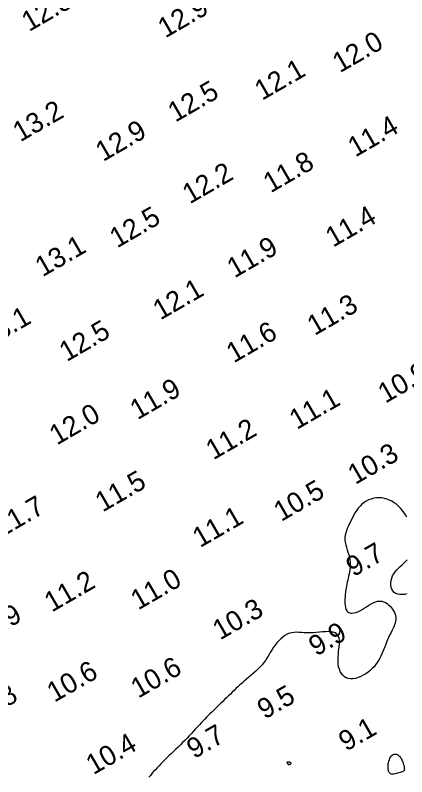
# Model space of a CAD drawing. Extents: x 3024098 to 3056816, y 418252 to 509144.
# Drawn here: x 3036317.9 to 3036415.8, y 419350.7 to 419541.3 of the extents above; entities that cross this region are included whole.
import ezdxf

# ---------------------------------------------------------------- set-up
doc = ezdxf.new("R2010")
doc.units = 0
doc.layers.add('V-CHAN-CONT-EL10', color=7, linetype='Continuous')
doc.layers.add('V-TOPO-SOUN-0911', color=7, linetype='Continuous')

msp = doc.modelspace()

# ---------------------------------------------------------------- linework, layer by layer
at = {"layer": 'V-CHAN-CONT-EL10'}
for points in [[(3036415.77, 419415.72), (3036415.43, 419416.31), (3036415.06, 419416.89), (3036414.64, 419417.44), (3036414.19, 419417.96), (3036413.7, 419418.45), (3036413.18, 419418.9), (3036412.62, 419419.31), (3036412.04, 419419.67), (3036411.44, 419419.97), (3036410.81, 419420.21), (3036410.17, 419420.39), (3036409.51, 419420.5), (3036408.84, 419420.54), (3036408.18, 419420.5), (3036407.52, 419420.4), (3036406.87, 419420.22), (3036406.24, 419419.99), (3036405.64, 419419.69), (3036405.08, 419419.34), (3036404.55, 419418.93), (3036404.08, 419418.48), (3036403.65, 419417.97), (3036403.25, 419417.44), (3036402.89, 419416.87), (3036402.56, 419416.29), (3036402.25, 419415.7), (3036401.96, 419415.1), (3036401.67, 419414.51), (3036401.4, 419413.94), (3036401.13, 419413.37), (3036400.89, 419412.82), (3036400.68, 419412.26), (3036400.51, 419411.71), (3036400.39, 419411.15), (3036400.32, 419410.58), (3036400.32, 419409.99), (3036400.39, 419409.4), (3036400.51, 419408.79), (3036400.68, 419408.17), (3036400.87, 419407.54), (3036401.07, 419406.91), (3036401.25, 419406.27), (3036401.42, 419405.64), (3036401.54, 419405.01), (3036401.6, 419404.39), (3036401.62, 419403.78), (3036401.6, 419403.18), (3036401.54, 419402.59), (3036401.45, 419402.02), (3036401.34, 419401.46), (3036401.23, 419400.92), (3036401.11, 419400.4), (3036401, 419399.9), (3036400.89, 419399.41), (3036400.79, 419398.93), (3036400.69, 419398.45), (3036400.61, 419397.97), (3036400.53, 419397.47), (3036400.45, 419396.96), (3036400.39, 419396.42), (3036400.34, 419395.86), (3036400.3, 419395.28), (3036400.28, 419394.7), (3036400.29, 419394.13), (3036400.34, 419393.59), (3036400.43, 419393.09), (3036400.57, 419392.66), (3036400.76, 419392.29), (3036401.01, 419392.02), (3036401.32, 419391.83), (3036401.68, 419391.71), (3036402.08, 419391.68), (3036402.52, 419391.73), (3036403, 419391.84), (3036403.51, 419392.02), (3036404.03, 419392.27), (3036404.58, 419392.57), (3036405.13, 419392.92), (3036405.7, 419393.28), (3036406.27, 419393.64), (3036406.83, 419393.98), (3036407.39, 419394.28), (3036407.94, 419394.51), (3036408.48, 419394.66), (3036409, 419394.71), (3036409.5, 419394.66), (3036409.97, 419394.53), (3036410.42, 419394.33), (3036410.84, 419394.06), (3036411.23, 419393.76), (3036411.59, 419393.41), (3036411.92, 419393.04), (3036412.21, 419392.66), (3036412.46, 419392.27), (3036412.67, 419391.86), (3036412.84, 419391.44), (3036412.95, 419391.01), (3036413.02, 419390.57), (3036413.03, 419390.12), (3036412.98, 419389.66), (3036412.87, 419389.19), (3036412.71, 419388.71), (3036412.51, 419388.22), (3036412.28, 419387.72), (3036412.02, 419387.21), (3036411.75, 419386.68), (3036411.48, 419386.14), (3036411.22, 419385.59), (3036410.97, 419385.02), (3036410.74, 419384.45), (3036410.51, 419383.86), (3036410.28, 419383.28), (3036410.05, 419382.69), (3036409.82, 419382.1), (3036409.57, 419381.52), (3036409.31, 419380.94), (3036409.02, 419380.38), (3036408.71, 419379.83), (3036408.36, 419379.29), (3036407.99, 419378.77), (3036407.58, 419378.27), (3036407.13, 419377.79), (3036406.64, 419377.33), (3036406.1, 419376.9), (3036405.52, 419376.5), (3036404.9, 419376.13), (3036404.25, 419375.81), (3036403.6, 419375.54), (3036402.95, 419375.35), (3036402.31, 419375.24), (3036401.71, 419375.21), (3036401.14, 419375.29), (3036400.63, 419375.48), (3036400.17, 419375.76), (3036399.77, 419376.13), (3036399.43, 419376.58), (3036399.14, 419377.08), (3036398.91, 419377.64), (3036398.74, 419378.24), (3036398.63, 419378.86), (3036398.58, 419379.49), (3036398.58, 419380.13), (3036398.61, 419380.78), (3036398.67, 419381.42), (3036398.74, 419382.06), (3036398.82, 419382.68), (3036398.88, 419383.28), (3036398.93, 419383.86), (3036398.94, 419384.41), (3036398.91, 419384.93), (3036398.83, 419385.4), (3036398.7, 419385.83), (3036398.49, 419386.2), (3036398.21, 419386.51), (3036397.85, 419386.75), (3036397.39, 419386.92), (3036396.83, 419387.02), (3036396.19, 419387.05), (3036395.49, 419387.03), (3036394.73, 419386.98), (3036393.95, 419386.91), (3036393.15, 419386.83), (3036392.35, 419386.77), (3036391.57, 419386.74), (3036390.83, 419386.75), (3036390.13, 419386.79), (3036389.45, 419386.83), (3036388.81, 419386.87), (3036388.19, 419386.89), (3036387.58, 419386.86), (3036387, 419386.78), (3036386.43, 419386.63), (3036385.86, 419386.39), (3036385.31, 419386.07), (3036384.77, 419385.68), (3036384.26, 419385.24), (3036383.77, 419384.75), (3036383.3, 419384.23), (3036382.86, 419383.69), (3036382.46, 419383.14), (3036382.09, 419382.59), (3036381.75, 419382.04), (3036381.42, 419381.49), (3036381.1, 419380.94), (3036380.76, 419380.4), (3036380.41, 419379.85), (3036380.03, 419379.31), (3036379.6, 419378.78), (3036379.12, 419378.24), (3036378.6, 419377.71), (3036378.05, 419377.18), (3036377.47, 419376.66), (3036376.88, 419376.15), (3036376.29, 419375.64), (3036375.7, 419375.14), (3036375.13, 419374.66), (3036374.59, 419374.18), (3036374.06, 419373.71), (3036373.56, 419373.25), (3036373.07, 419372.79), (3036372.6, 419372.34), (3036372.12, 419371.89), (3036371.66, 419371.44), (3036371.19, 419370.98), (3036370.71, 419370.52), (3036370.24, 419370.05), (3036369.76, 419369.59), (3036369.28, 419369.12), (3036368.81, 419368.66), (3036368.34, 419368.21), (3036367.88, 419367.76), (3036367.44, 419367.32), (3036367, 419366.88), (3036366.57, 419366.46), (3036366.14, 419366.04), (3036365.72, 419365.61), (3036365.29, 419365.17), (3036364.85, 419364.73), (3036364.4, 419364.26), (3036363.94, 419363.77), (3036363.46, 419363.25), (3036362.96, 419362.71), (3036362.45, 419362.16), (3036361.92, 419361.58), (3036361.39, 419361), (3036360.84, 419360.42), (3036360.28, 419359.84), (3036359.72, 419359.27), (3036359.16, 419358.71), (3036358.6, 419358.15), (3036358.04, 419357.61), (3036357.48, 419357.08), (3036356.92, 419356.55), (3036356.38, 419356.03), (3036355.84, 419355.52), (3036355.32, 419355.01), (3036354.81, 419354.5), (3036354.31, 419354), (3036353.83, 419353.5), (3036353.36, 419353), (3036352.92, 419352.51), (3036352.48, 419352.02), (3036352.07, 419351.54), (3036351.67, 419351.07), (3036351.29, 419350.6)], [(3036415.81, 419396.48), (3036415.22, 419396.36), (3036414.63, 419396.32), (3036414.06, 419396.35), (3036413.52, 419396.45), (3036413.04, 419396.63), (3036412.61, 419396.88), (3036412.26, 419397.22), (3036412.01, 419397.64), (3036411.84, 419398.12), (3036411.76, 419398.66), (3036411.77, 419399.23), (3036411.85, 419399.81), (3036412, 419400.4), (3036412.22, 419400.98), (3036412.51, 419401.52), (3036412.86, 419402.03), (3036413.26, 419402.49), (3036413.69, 419402.93), (3036414.14, 419403.35), (3036414.6, 419403.76), (3036415.05, 419404.17), (3036415.47, 419404.59), (3036415.86, 419405.03)]]:
    msp.add_lwpolyline(points, dxfattribs=at)
for points in [[(3036411.1, 419353.51), (3036411.14, 419353.89), (3036411.21, 419354.28), (3036411.3, 419354.66), (3036411.41, 419355.03), (3036411.55, 419355.37), (3036411.72, 419355.68), (3036411.92, 419355.94), (3036412.14, 419356.15), (3036412.38, 419356.3), (3036412.64, 419356.38), (3036412.91, 419356.41), (3036413.18, 419356.37), (3036413.45, 419356.27), (3036413.72, 419356.1), (3036413.96, 419355.86), (3036414.19, 419355.56), (3036414.4, 419355.21), (3036414.59, 419354.82), (3036414.75, 419354.41), (3036414.89, 419354), (3036415, 419353.6), (3036415.08, 419353.24), (3036415.13, 419352.92), (3036415.16, 419352.67), (3036415.15, 419352.47), (3036415.11, 419352.32), (3036415.04, 419352.21), (3036414.92, 419352.11), (3036414.78, 419352.04), (3036414.59, 419351.97), (3036414.37, 419351.89), (3036414.1, 419351.8), (3036413.81, 419351.7), (3036413.49, 419351.6), (3036413.17, 419351.52), (3036412.84, 419351.45), (3036412.52, 419351.4), (3036412.22, 419351.38), (3036411.96, 419351.41), (3036411.73, 419351.48), (3036411.54, 419351.6), (3036411.38, 419351.77), (3036411.26, 419351.97), (3036411.18, 419352.21), (3036411.12, 419352.49), (3036411.08, 419352.8), (3036411.08, 419353.14)], [(3036385.95, 419354.14), (3036385.92, 419354.18), (3036385.88, 419354.22), (3036385.86, 419354.26), (3036385.83, 419354.3), (3036385.83, 419354.34), (3036385.83, 419354.37), (3036385.85, 419354.4), (3036385.88, 419354.43), (3036385.94, 419354.45), (3036386, 419354.47), (3036386.08, 419354.48), (3036386.16, 419354.48), (3036386.24, 419354.48), (3036386.32, 419354.48), (3036386.4, 419354.46), (3036386.47, 419354.44), (3036386.54, 419354.42), (3036386.59, 419354.39), (3036386.65, 419354.35), (3036386.69, 419354.31), (3036386.73, 419354.27), (3036386.75, 419354.23), (3036386.78, 419354.19), (3036386.79, 419354.15), (3036386.8, 419354.1), (3036386.8, 419354.06), (3036386.79, 419354.02), (3036386.77, 419353.98), (3036386.74, 419353.94), (3036386.71, 419353.9), (3036386.66, 419353.87), (3036386.61, 419353.84), (3036386.55, 419353.82), (3036386.49, 419353.79), (3036386.42, 419353.78), (3036386.36, 419353.76), (3036386.3, 419353.76), (3036386.24, 419353.76), (3036386.2, 419353.76), (3036386.17, 419353.77), (3036386.15, 419353.79), (3036386.13, 419353.81), (3036386.13, 419353.83), (3036386.12, 419353.85), (3036386.12, 419353.88), (3036386.12, 419353.91), (3036386.12, 419353.93), (3036386.12, 419353.95), (3036386.11, 419353.97), (3036386.1, 419353.99), (3036386.08, 419354.01), (3036386.06, 419354.03), (3036386.04, 419354.05), (3036386.02, 419354.08), (3036385.98, 419354.11)]]:
    msp.add_lwpolyline(points, close=True, dxfattribs=at)

# ---------------------------------------------------------------- texts
at = {"layer": 'V-TOPO-SOUN-0911'}
for s, p in [('12.8 ', (3036321.34, 419537.05)), ('12.9 ', (3036355.4, 419535.44)), ('12.0 ', (3036399.05, 419526.74)), ('12.1 ', (3036379.59, 419519.84)), ('12.5 ', (3036357.91, 419514.38)), ('13.2 ', (3036319.14, 419509.45)), ('11.4 ', (3036402.9, 419505.65)), ('12.9 ', (3036339.84, 419504.53)), ('11.8 ', (3036381.74, 419496.69)), ('12.2 ', (3036361.53, 419493.94)), ('12.5 ', (3036343.34, 419482.91)), ('11.4 ', (3036397.32, 419483.08)), ('13.1 ', (3036324.73, 419475.71)), ('11.9 ', (3036372.69, 419475.4)), ('12.1 ', (3036354.16, 419464.88)), ('11.3 ', (3036392.73, 419461)), ('13.1 ', (3036310.96, 419457.93)), ('12.5 ', (3036330.75, 419454.47)), ('11.6 ', (3036372.52, 419454.15)), ('10.9 ', (3036410.42, 419444.07)), ('11.9 ', (3036348.44, 419439.93)), ('11.1 ', (3036388.28, 419437.49)), ('12.0 ', (3036328.28, 419433.6)), ('11.2 ', (3036367.4, 419429.89)), ('10.3 ', (3036402.9, 419423.73)), ('11.5 ', (3036339.74, 419416.84)), ('10.5 ', (3036384.36, 419414.47)), ('11.7 ', (3036314.39, 419410.5)), ('11.1 ', (3036364.07, 419407.93)), ('9.7', (3036402.44, 419400.64)), ('11.0 ', (3036348.62, 419392.33)), ('11.2 ', (3036327.02, 419391.8)), ('10.3 ', (3036369.08, 419384.82)), ('10.9 ', (3036308.68, 419383.47)), ('9.9', (3036393.12, 419380.79)), ('10.6 ', (3036327.67, 419369.24)), ('10.6 ', (3036348.64, 419370.25)), ('9.8', (3036310.87, 419365.3)), ('9.5', (3036380.25, 419365.01)), ('9.1', (3036400.59, 419356.98)), ('9.7', (3036362.61, 419355.13)), ('10.4 ', (3036337.42, 419351.12))]:
    msp.add_text(s, height=5, rotation=30, dxfattribs=at).set_placement(p)

doc.saveas('drawing.dxf')
